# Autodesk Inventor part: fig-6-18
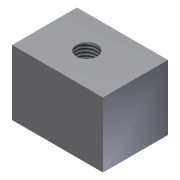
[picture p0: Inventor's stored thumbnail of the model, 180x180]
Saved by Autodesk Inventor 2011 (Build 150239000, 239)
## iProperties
Created: 2009-09
Part Number: fig-6-18
Document SubType Name: Modeling
Designer: Sham
Density: 1 g/cm^3
Author: Sham
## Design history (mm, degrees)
sketch "Sketch1"
  geometry: L1 (-28, 20)-(0, 20); L2 (0, 20)-(0, 0); L3 (0, 0)-(-28, 0); L4 (-28, 0)-(-28, 20)
  constraints: 8 end point, 2 parallel, 1 horizontal, 1 perpendicular
extrude "Extrusion1" new body sketch "Sketch1" distance "d0" = 20; taper "d1" = 0 deg
hole "Hole1" diameter "d4" = 5.944; stored, may be unused: countersink angle "d8" = 90 deg, drill point angle "d10" = 118 deg; dims "d2" = 10, "d3" = 15, "d5" = 5.946, "d6" = 12, "d7" = 3, "d9" = 15, "d11" = 0.62479, "d12" = 5.994
body "Solid1"
